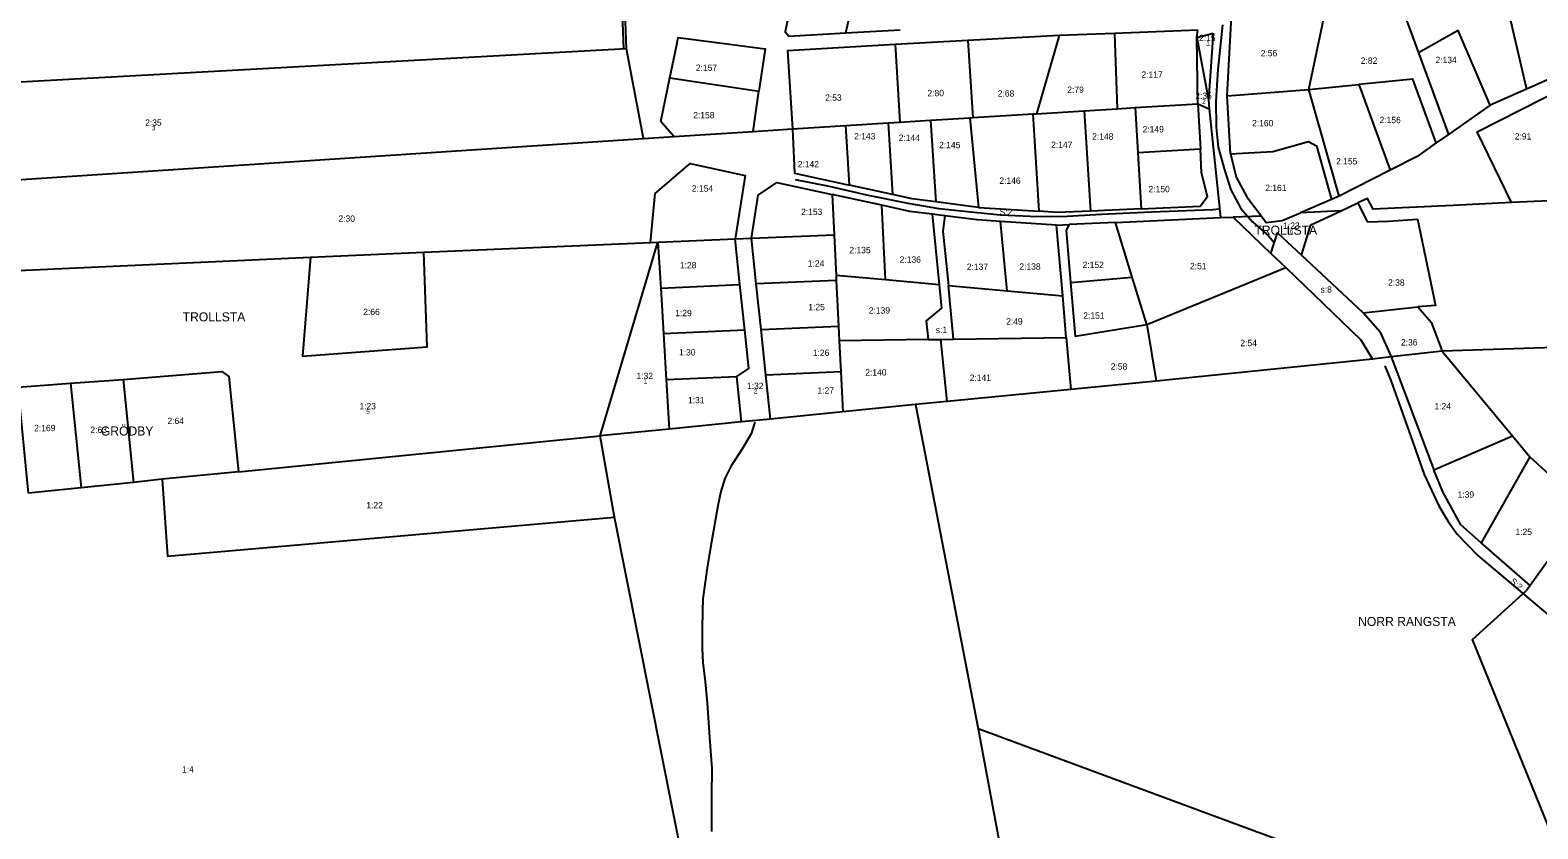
# Model space of a CAD drawing. Extents: x 140824 to 143748, y 6547319 to 6550906.
# Drawn here: x 141835 to 142666, y 6547892 to 6548333 of the extents above; entities that cross this region are included whole.
import ezdxf

# ---------------------------------------------------------------- set-up
doc = ezdxf.new("R2010")
doc.units = 0
for name, color, linetype in [('FAST Fastighetsgräns', 7, 'Continuous'), ('FAST Mittlinjeredovisad samfällighet', 7, 'Continuous'), ('FAST Områdesnummer för fastighet', 7, 'Continuous'), ('FAST Registernummer för fastighet', 7, 'Continuous'), ('FAST Registernummer för mittlinjeredovisad samfällighet', 7, 'Continuous'), ('FAST Registernummer för samfällighet', 7, 'Continuous'), ('FAST Traktgräns', 7, 'Continuous'), ('FAST Traktnamn', 7, 'Continuous')]:
    doc.layers.add(name, color=color, linetype=linetype)

msp = doc.modelspace()

# ---------------------------------------------------------------- linework, layer by layer
at = {"layer": 'FAST Fastighetsgräns'}
for p, q in [((142284.43, 6548331.36), (142293.29, 6548370.64)), ((142645.15, 6548362.91), (142659.85, 6548300.41)), ((142539.85, 6548300.23), (142548.71, 6548343.09)), ((142591.08, 6548345.34), (142600.25, 6548320.44)), ((142284.43, 6548331.36), (142314.4, 6548333.04)), ((142478.66, 6548332.81), (142432.68, 6548331.08)), ((142477.94, 6548328.9), (142478.66, 6548332.81)), ((142494.77, 6548296.57), (142497.13, 6548340.5)), ((142351.73, 6548327.17), (142311.76, 6548324.92)), ((142311.76, 6548324.92), (142314.32, 6548282.16)), ((142402.19, 6548329.94), (142351.73, 6548327.17)), ((142351.73, 6548327.17), (142354.46, 6548284.66)), ((142402.19, 6548329.94), (142389.53, 6548286.78)), ((142432.68, 6548331.08), (142402.19, 6548329.94)), ((142432.68, 6548331.08), (142434.16, 6548289.52)), ((142477.94, 6548328.9), (142487, 6548331.3)), ((142477.94, 6548328.9), (142484.48, 6548294.4)), ((142478.64, 6548292.26), (142477.94, 6548328.9)), ((142487, 6548331.3), (142484.48, 6548294.4)), ((142163.49, 6548322.6), (141775.28, 6548301.31)), ((142172.85, 6548273.2), (142163.49, 6548322.6)), ((142600.25, 6548320.44), (142616.85, 6548275.4)), ((142187.45, 6548306.66), (142236.6, 6548299.22)), ((142233.3, 6548277.04), (142236.6, 6548299.22)), ((142494.77, 6548296.57), (142539.85, 6548300.23)), ((142539.85, 6548300.23), (142567.4, 6548302.86)), ((142556.48, 6548241.29), (142539.85, 6548300.23)), ((142567.4, 6548302.86), (142584.61, 6548255.61)), ((142659.85, 6548300.41), (142639.76, 6548291.51)), ((142443.94, 6548290.13), (142478.64, 6548292.26)), ((142478.64, 6548292.26), (142479.96, 6548267.25)), ((142478.64, 6548292.26), (142484.84, 6548289.42)), ((142484.48, 6548294.4), (142484.84, 6548289.42)), ((142496.52, 6548264.61), (142494.77, 6548296.57)), ((142639.76, 6548291.51), (142616.85, 6548275.4)), ((142314.32, 6548282.16), (142331.24, 6548283.22)), ((142331.24, 6548283.22), (142352.86, 6548284.56)), ((142331.24, 6548283.22), (142334.06, 6548238.15)), ((142352.86, 6548284.56), (142354.46, 6548284.66)), ((142352.86, 6548284.56), (142357.63, 6548235.12)), ((142354.46, 6548284.66), (142387.75, 6548286.7)), ((142387.75, 6548286.7), (142389.53, 6548286.78)), ((142391.04, 6548232.96), (142387.75, 6548286.7)), ((142389.53, 6548286.78), (142415.95, 6548288.42)), ((142415.95, 6548288.42), (142434.16, 6548289.52)), ((142415.95, 6548288.42), (142419.33, 6548233.1)), ((142434.16, 6548289.52), (142443.94, 6548290.13)), ((142443.94, 6548290.13), (142445.47, 6548265.14)), ((142484.84, 6548289.42), (142491.1, 6548229.5)), ((142189.55, 6548274.21), (142233.3, 6548277.04)), ((142233.3, 6548277.04), (142255.02, 6548278.47)), ((142255.02, 6548278.47), (142284.42, 6548280.29)), ((142284.42, 6548280.29), (142307.83, 6548281.75)), ((142286.47, 6548247.34), (142284.42, 6548280.29)), ((142307.83, 6548281.75), (142314.32, 6548282.16)), ((142307.83, 6548281.75), (142310.3, 6548242.16)), ((142616.85, 6548275.4), (142610, 6548270.64)), ((141587.01, 6548234.32), (142172.85, 6548273.2)), ((142172.85, 6548273.2), (142189.55, 6548274.21)), ((142479.96, 6548267.25), (142445.47, 6548265.14)), ((142445.47, 6548265.14), (142447.36, 6548234.32)), ((142496.52, 6548264.61), (142499.78, 6548251.8)), ((142499.78, 6548251.8), (142505.51, 6548240.97)), ((142584.61, 6548255.61), (142556.48, 6548241.29)), ((142276.89, 6548242.25), (142277.98, 6548220.02)), ((142304.25, 6548236.29), (142276.89, 6548242.25)), ((142310.3, 6548242.16), (142286.47, 6548247.34)), ((142556.48, 6548241.29), (142552.31, 6548239.51)), ((142306.28, 6548195.02), (142304.25, 6548236.29)), ((142357.63, 6548235.12), (142334.06, 6548238.15)), ((142357.63, 6548235.12), (142391.04, 6548232.96)), ((142447.36, 6548234.32), (142419.33, 6548233.1)), ((142505.51, 6548240.97), (142513.65, 6548230.31)), ((142552.31, 6548239.51), (142535.15, 6548232.15)), ((142557.57, 6548233.22), (142566.78, 6548237.53)), ((142339.14, 6548230.42), (142332.08, 6548231.34)), ((142332.08, 6548231.34), (142335.93, 6548192.36)), ((142400.7, 6548225.31), (142369.71, 6548227.31)), ((142373.51, 6548188.98), (142369.71, 6548227.31)), ((142400.7, 6548225.31), (142407.7, 6548225.6)), ((142404.07, 6548186.23), (142400.7, 6548225.31)), ((142433.09, 6548226.67), (142407.7, 6548225.6)), ((142433.09, 6548226.67), (142491.1, 6548229.5)), ((142442.39, 6548196.62), (142433.09, 6548226.67)), ((142491.1, 6548229.5), (142498.11, 6548229.72)), ((142226.07, 6548192.48), (142223.43, 6548217.67)), ((142235.09, 6548192.87), (142232.45, 6548218.06)), ((141989.34, 6548207.6), (142051.78, 6548210.46)), ((142149.1, 6548109.02), (142180.91, 6548215.84)), ((142180.91, 6548215.84), (142182.42, 6548190.6)), ((142518.89, 6548209.58), (142527.13, 6548201.91)), ((142569.78, 6548176.95), (142535.76, 6548208.66)), ((142450.44, 6548170.52), (142527.13, 6548201.91)), ((142182.42, 6548190.6), (142226.07, 6548192.48)), ((142228.71, 6548167.3), (142226.07, 6548192.48)), ((142279.23, 6548194.78), (142235.09, 6548192.87)), ((142237.74, 6548167.69), (142235.09, 6548192.87)), ((142306.28, 6548195.02), (142279.09, 6548197.46)), ((142335.93, 6548192.36), (142306.28, 6548195.02)), ((142341.01, 6548191.9), (142373.51, 6548188.98)), ((142343.94, 6548162.34), (142341.01, 6548191.9)), ((142408.45, 6548193.7), (142442.39, 6548196.62)), ((142450.44, 6548170.52), (142442.39, 6548196.62)), ((142182.42, 6548190.6), (142183.94, 6548165.36)), ((142373.51, 6548188.98), (142404.07, 6548186.23)), ((142406.06, 6548163.28), (142404.07, 6548186.23)), ((142569.78, 6548176.95), (142599.96, 6548180.13)), ((142579.15, 6548166.3), (142569.78, 6548176.95)), ((142228.71, 6548167.3), (142183.94, 6548165.36)), ((142237.74, 6548167.69), (142280.46, 6548169.53)), ((142240.38, 6548142.5), (142237.74, 6548167.69)), ((142450.44, 6548170.52), (142455.67, 6548139.24)), ((142579.15, 6548166.3), (142585.14, 6548152.59)), ((142183.94, 6548165.36), (142185.45, 6548140.14)), ((142329.86, 6548162.13), (142280.86, 6548161.39)), ((142329.86, 6548162.13), (142336.9, 6548162.24)), ((142336.9, 6548162.24), (142343.94, 6548162.34)), ((142340.28, 6548127.9), (142336.9, 6548162.24)), ((142343.94, 6548162.34), (142406.06, 6548163.28)), ((142406.06, 6548163.28), (142408.53, 6548134.65)), ((142585.14, 6548152.59), (142608.77, 6548090.27)), ((142613.33, 6548155.79), (142652.11, 6548109.04)), ((142185.45, 6548140.14), (142224.34, 6548141.81)), ((142226.96, 6548116.71), (142224.34, 6548141.81)), ((142281.7, 6548144.28), (142240.38, 6548142.5)), ((142242.91, 6548118.29), (142240.38, 6548142.5)), ((141857.05, 6548138.01), (141862.77, 6548080.36)), ((141886.04, 6548140.17), (141891.65, 6548083.28)), ((142185.45, 6548140.14), (142187.09, 6548112.77)), ((142322.92, 6548126.25), (142357.53, 6547947.34)), ((142156.88, 6548064.06), (142149.1, 6548109.02)), ((142608.77, 6548090.27), (142652.11, 6548109.04)), ((142652.11, 6548109.04), (142661.71, 6548097.46)), ((142661.71, 6548097.46), (142634.79, 6548049.99)), ((142661.71, 6548097.46), (142692.38, 6548069.07)), ((142692.38, 6548069.07), (142661.74, 6548026.47)), ((142634.79, 6548049.99), (142623.52, 6548059.86)), ((142661.74, 6548026.47), (142634.79, 6548049.99)), ((142661.74, 6548026.47), (142659.74, 6548023.7))]:
    msp.add_line(p, q, dxfattribs=at)
for points in [[(142163.49, 6548322.6), (142158.09, 6548472.86), (142206.82, 6548487.8)], [(142258.62, 6548368.66), (142250.96, 6548331.92), (142252.99, 6548329.6), (142284.43, 6548331.36)], [(142639.76, 6548291.51), (142622.08, 6548332.63), (142600.25, 6548320.44)], [(142187.45, 6548306.66), (142191.06, 6548324.05), (142192.07, 6548328.89), (142240.08, 6548322.59), (142236.6, 6548299.22)], [(142311.76, 6548324.92), (142252.36, 6548321.56), (142255.02, 6548278.47)], [(142701.23, 6548314.47), (142677.59, 6548308.34), (142659.85, 6548300.41)], [(142189.55, 6548274.21), (142182.41, 6548282.46), (142187.45, 6548306.66)], [(142610, 6548270.64), (142597.18, 6548305.79), (142567.4, 6548302.86)], [(142651.5, 6548237.73), (142632.54, 6548276.83), (142680.48, 6548301.15)], [(142255.02, 6548278.47), (142256.19, 6548253.93), (142286.47, 6548247.34)], [(142447.36, 6548234.32), (142479.84, 6548235.78), (142483.84, 6548241.11), (142480.65, 6548254.25), (142479.96, 6548267.25)], [(142496.52, 6548264.61), (142519.98, 6548265.91), (142539.65, 6548271.44), (142543.99, 6548269.01), (142552.31, 6548239.51)], [(142610, 6548270.64), (142599.49, 6548263.21), (142584.61, 6548255.61)], [(142176.69, 6548215.66), (142179.29, 6548242.76), (142198.58, 6548259.29), (142228.9, 6548252.69), (142223.43, 6548217.67)], [(142232.45, 6548218.06), (142236.18, 6548241.9), (142246.38, 6548248.89), (142276.89, 6548242.25)], [(142334.06, 6548238.15), (142321.01, 6548239.83), (142310.3, 6548242.16)], [(142332.08, 6548231.34), (142319.82, 6548232.91), (142304.25, 6548236.29)], [(142419.33, 6548233.1), (142400.78, 6548232.33), (142391.04, 6548232.96)], [(142339.14, 6548230.42), (142338.04, 6548221.92), (142341.01, 6548191.9)], [(142369.71, 6548227.31), (142356.82, 6548228.14), (142339.14, 6548230.42)], [(142407.7, 6548225.6), (142405.95, 6548222.52), (142408.45, 6548193.7)], [(142527.13, 6548201.91), (142568.51, 6548162.04), (142574.89, 6548151.39)], [(142335.93, 6548192.36), (142337.22, 6548179.4), (142328.82, 6548172.53), (142329.86, 6548162.13)], [(142408.45, 6548193.7), (142411.02, 6548164.09), (142450.44, 6548170.52)], [(142224.34, 6548141.81), (142230.93, 6548146.09), (142228.71, 6548167.3)], [(141907.49, 6548085.1), (141910.45, 6548042.58), (142156.88, 6548064.06)], [(142623.52, 6548059.86), (142613.75, 6548078.09), (142608.77, 6548090.27)], [(142160.23, 6547730.93), (142157.6, 6547744), (142161.92, 6547754.88), (142171.18, 6547763.62), (142182.34, 6547769.3), (142196.65, 6547779.9), (142204.97, 6547790.66), (142209.25, 6547800.54), (142156.88, 6548064.06)], [(142710.21, 6547901.25), (142671.97, 6547893.34), (142629.96, 6547996.54), (142659.74, 6548023.7)]]:
    msp.add_lwpolyline(points, dxfattribs=at)
at = {"layer": 'FAST Mittlinjeredovisad samfällighet'}
msp.add_line((142157.05, 6548467.7), (142161.8, 6548322.48), dxfattribs=at)
for points in [[(142492.27, 6548335.76), (142489.65, 6548311.19), (142488.42, 6548293.78), (142488.74, 6548279.4), (142489.74, 6548268.37), (142493.19, 6548255.8), (142496.83, 6548244.84), (142502.26, 6548234.57), (142508.79, 6548227.05), (142517.51, 6548219.31), (142520.73, 6548215.7)], [(142256.5, 6548250.44), (142275.26, 6548246.85), (142295.95, 6548241.99), (142318.7, 6548237.38), (142335.78, 6548234.39), (142351.57, 6548232.76), (142369.85, 6548230.91), (142386.11, 6548230.3), (142403.42, 6548230.09), (142425.45, 6548231.36), (142453.06, 6548232.62), (142486.84, 6548233.99), (142490.59, 6548234.32)], [(142581.63, 6548147.56), (142585.08, 6548139.58), (142596.03, 6548108.56), (142603.35, 6548087.62), (142611.48, 6548070.4), (142616.66, 6548061.74), (142621.56, 6548054.74), (142632.99, 6548043.03), (142677.52, 6548005.37), (142699.43, 6547986.09), (142731.1, 6547958.97), (142762.42, 6547931.66)], [(142234.26, 6548116.58), (142232.21, 6548110.03), (142226.61, 6548100.59), (142221.28, 6548092.48), (142217.78, 6548085.41), (142215.52, 6548078.25), (142213.91, 6548070.32), (142210.5, 6548050.52), (142208.23, 6548037.49), (142205.55, 6548019.09), (142205.39, 6548012.3), (142205.21, 6548002.3), (142205.21, 6547991.69), (142205.57, 6547983.83), (142206.89, 6547973.28), (142208.1, 6547961.69), (142209.25, 6547942.5), (142210.67, 6547925.36), (142210.33, 6547910.44), (142210.35, 6547890.57)]]:
    msp.add_lwpolyline(points, dxfattribs=at)
at = {"layer": 'FAST Traktgräns'}
for p, q in [((142557.57, 6548233.22), (142535.15, 6548232.15)), ((142540.87, 6548225.42), (142557.57, 6548233.22)), ((142566.78, 6548237.53), (142572.01, 6548227.12)), ((142697.01, 6548239.92), (142651.5, 6548237.73)), ((142513.65, 6548230.31), (142498.11, 6548229.72)), ((142498.11, 6548229.72), (142518.89, 6548209.58)), ((142535.76, 6548208.66), (142540.87, 6548225.42)), ((142180.91, 6548215.84), (142223.43, 6548217.67)), ((142223.43, 6548217.67), (142232.45, 6548218.06)), ((142232.45, 6548218.06), (142277.98, 6548220.02)), ((142277.98, 6548220.02), (142279.09, 6548197.46)), ((142051.78, 6548210.46), (142176.69, 6548215.66)), ((142176.69, 6548215.66), (142180.91, 6548215.84)), ((141768.09, 6548197.47), (141989.34, 6548207.6)), ((142279.09, 6548197.46), (142279.23, 6548194.78)), ((142279.23, 6548194.78), (142280.46, 6548169.53)), ((142599.96, 6548180.13), (142607.32, 6548171.77)), ((142280.46, 6548169.53), (142280.86, 6548161.39)), ((142607.32, 6548171.77), (142613.33, 6548155.79)), ((142280.86, 6548161.39), (142281.7, 6548144.28)), ((142574.89, 6548151.39), (142455.67, 6548139.24)), ((142585.14, 6548152.59), (142574.89, 6548151.39)), ((142613.33, 6548155.79), (142585.14, 6548152.59)), ((142281.7, 6548144.28), (142282.78, 6548122.22)), ((141857.05, 6548138.01), (141886.04, 6548140.17)), ((142408.53, 6548134.65), (142340.28, 6548127.9)), ((142455.67, 6548139.24), (142408.53, 6548134.65)), ((142322.92, 6548126.25), (142282.78, 6548122.22)), ((142340.28, 6548127.9), (142322.92, 6548126.25)), ((142226.96, 6548116.71), (142187.09, 6548112.77)), ((142242.91, 6548118.29), (142226.96, 6548116.71)), ((142282.78, 6548122.22), (142242.91, 6548118.29)), ((141949.54, 6548089.21), (142149.1, 6548109.02)), ((142187.09, 6548112.77), (142149.1, 6548109.02)), ((141891.65, 6548083.28), (141862.77, 6548080.36)), ((141907.49, 6548085.1), (141891.65, 6548083.28)), ((141949.54, 6548089.21), (141907.49, 6548085.1)), ((141862.77, 6548080.36), (141833.88, 6548077.44)), ((142357.53, 6547947.34), (142409.38, 6547666.8)), ((142922.53, 6547738.17), (142357.53, 6547947.34))]:
    msp.add_line(p, q, dxfattribs=at)
for points in [[(142651.5, 6548237.73), (142619.39, 6548236.14), (142575.23, 6548234.07), (142572.22, 6548240.07), (142566.78, 6548237.53)], [(142513.65, 6548230.31), (142516.19, 6548226.79), (142525.13, 6548227.85), (142535.15, 6548232.15)], [(142572.01, 6548227.12), (142583.78, 6548227.58), (142599.75, 6548228.55), (142609.56, 6548180.88), (142599.96, 6548180.13)], [(142518.89, 6548209.58), (142522.43, 6548221.09), (142535.76, 6548208.66)], [(141989.34, 6548207.6), (141984.85, 6548152.96), (142053.68, 6548158.2), (142051.78, 6548210.46)], [(143355.14, 6548066.67), (143319.95, 6548061.86), (142731.69, 6548159.66), (142613.33, 6548155.79)], [(141886.04, 6548140.17), (141940.47, 6548144.45), (141944.2, 6548141.81), (141949.54, 6548089.21)], [(141833.88, 6548077.44), (141828.06, 6548135.85), (141857.05, 6548138.01)]]:
    msp.add_lwpolyline(points, dxfattribs=at)

# ---------------------------------------------------------------- texts
at = {"layer": 'FAST Områdesnummer för fastighet'}
for s, p in [('1', (142483.26, 6548324.38)), ('2', (142480.97, 6548292.41)), ('3', (141901.87, 6548277.62)), ('6', (142529.36, 6548220.75)), ('1', (142173.02, 6548137.84)), ('2', (142233.7, 6548132.32)), ('5', (142020.03, 6548121.19))]:
    msp.add_text(s, height=2.5, dxfattribs=at).set_placement(p)
at = {"layer": 'FAST Registernummer för fastighet'}
for s, p in [('2:15', (142479.25, 6548326.88)), ('2:56', (142513.27, 6548318.49)), ('2:82', (142568.43, 6548314.32)), ('2:134', (142609.61, 6548314.69)), ('2:157', (142201.76, 6548310.44)), ('2:117', (142447.48, 6548306.61)), ('2:80', (142329.48, 6548296.44)), ('2:68', (142368.27, 6548296.26)), ('2:79', (142406.6, 6548298.28)), ('2:53', (142273.09, 6548293.93)), ('2:35', (142477.19, 6548294.91)), ('2:35', (141898.1, 6548280.12)), ('2:158', (142200.35, 6548284.24)), ('2:160', (142508.5, 6548279.85)), ('2:156', (142578.76, 6548281.58)), ('2:143', (142289.06, 6548272.58)), ('2:144', (142313.64, 6548271.78)), ('2:148', (142420.32, 6548272.49)), ('2:149', (142448.1, 6548276.45)), ('2:91', (142653.33, 6548272.55)), ('2:145', (142335.9, 6548267.77)), ('2:147', (142397.68, 6548267.92)), ('2:142', (142257.97, 6548257.21)), ('2:155', (142554.81, 6548258.8)), ('2:146', (142369.16, 6548248.09)), ('2:154', (142199.58, 6548243.82)), ('2:150', (142451.39, 6548243.46)), ('2:161', (142515.73, 6548244.1)), ('2:153', (142259.82, 6548230.91)), ('2:30', (142004.7, 6548227.15)), ('1:23', (142525.61, 6548223.25)), ('2:135', (142286.44, 6548209.81)), ('2:136', (142314.16, 6548204.53)), ('1:28', (142192.98, 6548201.45)), ('1:24', (142263.53, 6548202.41)), ('2:137', (142351.2, 6548200.58)), ('2:138', (142380.17, 6548200.72)), ('2:152', (142415.02, 6548201.64)), ('2:51', (142474.25, 6548200.97)), ('2:38', (142583.48, 6548191.9)), ('2:66', (142018.36, 6548175.7)), ('1:29', (142190.4, 6548175.05)), ('1:25', (142263.81, 6548178.35)), ('2:139', (142297.13, 6548176.5)), ('2:151', (142415.42, 6548173.63)), ('2:49', (142372.88, 6548170.39)), ('2:54', (142502.04, 6548158.5)), ('2:36', (142590.6, 6548158.87)), ('1:30', (142192.5, 6548153.36)), ('1:26', (142266.27, 6548153.13)), ('1:32', (142169.05, 6548140.34)), ('2:140', (142295.18, 6548142.29)), ('2:141', (142352.8, 6548139.32)), ('2:58', (142430.55, 6548145.54)), ('1:32', (142229.95, 6548134.82)), ('1:27', (142268.87, 6548132.27)), ('1:23', (142016.29, 6548123.69)), ('1:31', (142197.43, 6548126.98)), ('1:24', (142609.05, 6548123.56)), ('2:64', (141910.43, 6548115.52)), ('2:169', (141836.92, 6548111.58)), ('2:63', (141867.94, 6548110.6)), ('1:39', (142621.78, 6548074.89)), ('1:22', (142020.07, 6548068.97)), ('1:25', (142653.7, 6548054.28)), ('1:4', (141918.46, 6547923.19))]:
    msp.add_text(s, height=3.5, dxfattribs=at).set_placement(p)
at = {"layer": 'FAST Registernummer för mittlinjeredovisad samfällighet'}
for rotation, p in [(358.099, (142369.17, 6548230.92)), (319.71, (142650.5, 6548028.23))]:
    msp.add_text('S:2', height=3.5, rotation=rotation, dxfattribs=at).set_placement(p)
at = {"layer": 'FAST Registernummer för samfällighet'}
for s, p in [('s:8', (142546.25, 6548188.03)), ('s:1', (142334.11, 6548165.72))]:
    msp.add_text(s, height=3.5, dxfattribs=at).set_placement(p)
at = {"layer": 'FAST Traktnamn'}
for s, p in [('TROLLSTA', (142509.78, 6548220.03)), ('TROLLSTA', (141918.81, 6548172.18)), ('GRÖDBY', (141873.69, 6548109.19)), ('NORR RANGSTA', (142566.96, 6548004.05))]:
    msp.add_text(s, height=5, dxfattribs=at).set_placement(p)

doc.saveas('drawing.dxf')
